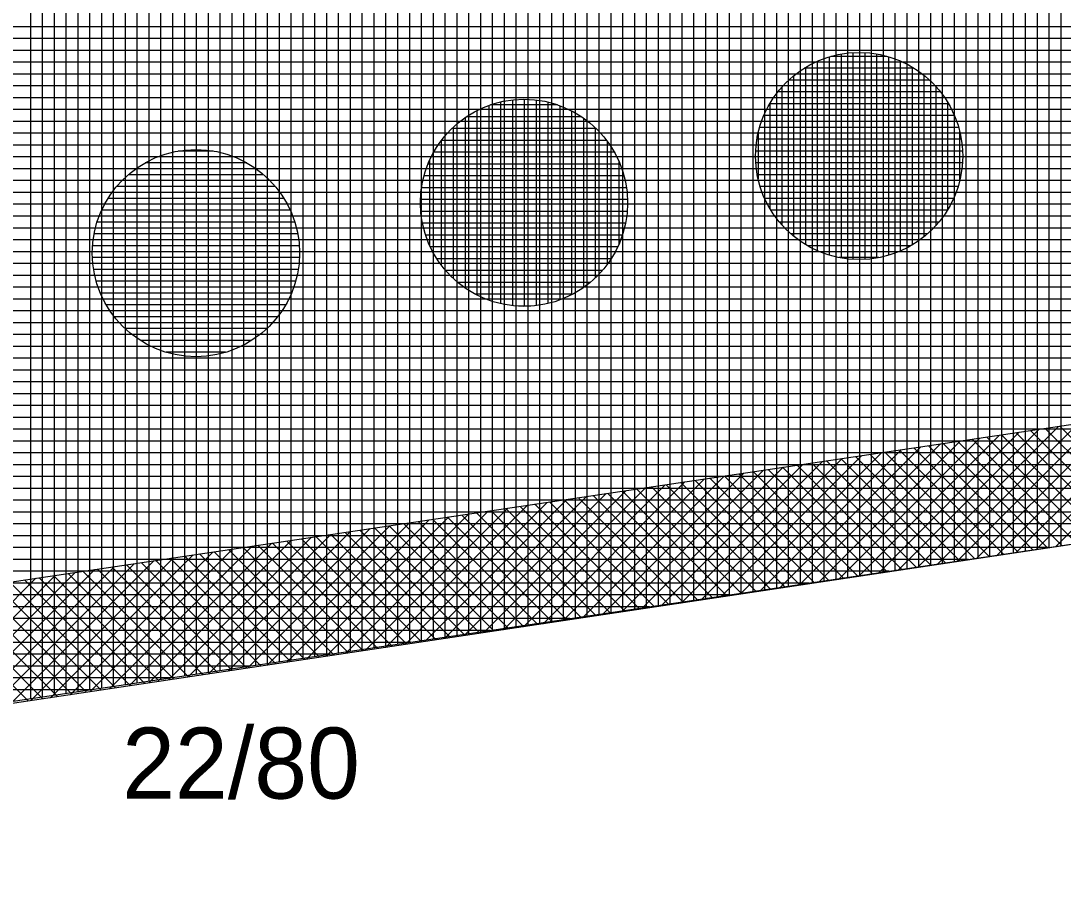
# Model space of a CAD drawing. Extents: x -565346 to -564154, y -1097386 to -1095620.
# Drawn here: x -564897.63 to -564880.03, y -1095809.07 to -1095794.48 of the extents above; entities that cross this region are included whole.
import ezdxf

# ---------------------------------------------------------------- set-up
doc = ezdxf.new("R2010")
doc.units = 0
for name, color, linetype in [('Vrstva 1', 7, 'Continuous'), ('Vrstva 40', 7, 'Continuous'), ('Vrstva 41', 7, 'Continuous'), ('Vrstva 42', 7, 'Continuous'), ('Vrstva 43', 7, 'Continuous'), ('Vrstva 44', 7, 'Continuous')]:
    doc.layers.add(name, color=color, linetype=linetype)

msp = doc.modelspace()

# ---------------------------------------------------------------- linework, layer by layer
at = {"layer": 'Vrstva 1'}
msp.add_line((-565025.24, -1095824.91), (-564877.52, -1095802.97), dxfattribs=at)
at = {"layer": 'Vrstva 41'}
for p, q in [((-564880.492, -1095803.416), (-564878.112, -1095801.036)), ((-564880.159, -1095803.366), (-564877.778, -1095800.985)), ((-564881.49, -1095803.566), (-564879.108, -1095801.184)), ((-564881.157, -1095803.516), (-564878.776, -1095801.135)), ((-564880.825, -1095803.466), (-564878.444, -1095801.086)), ((-564882.821, -1095803.766), (-564880.437, -1095801.382)), ((-564882.489, -1095803.716), (-564880.105, -1095801.332)), ((-564882.156, -1095803.666), (-564879.773, -1095801.283)), ((-564881.823, -1095803.616), (-564879.44, -1095801.234)), ((-564878.815, -1095803.165), (-564880.578, -1095801.402)), ((-564878.57, -1095803.128), (-564880.331, -1095801.366)), ((-564878.324, -1095803.091), (-564880.085, -1095801.329)), ((-564884.153, -1095803.966), (-564881.766, -1095801.579)), ((-564883.82, -1095803.916), (-564881.434, -1095801.53)), ((-564883.487, -1095803.866), (-564881.101, -1095801.48)), ((-564883.154, -1095803.816), (-564880.769, -1095801.431)), ((-564879.799, -1095803.312), (-564881.563, -1095801.549)), ((-564879.553, -1095803.275), (-564881.316, -1095801.512)), ((-564879.307, -1095803.238), (-564881.07, -1095801.476)), ((-564879.061, -1095803.201), (-564880.824, -1095801.439)), ((-564885.151, -1095804.116), (-564882.762, -1095801.727)), ((-564884.818, -1095804.066), (-564882.43, -1095801.678)), ((-564884.486, -1095804.016), (-564882.098, -1095801.628)), ((-564881.029, -1095803.497), (-564882.794, -1095801.732)), ((-564880.783, -1095803.46), (-564882.548, -1095801.695)), ((-564880.537, -1095803.423), (-564882.301, -1095801.658)), ((-564880.291, -1095803.386), (-564882.055, -1095801.622)), ((-564880.045, -1095803.349), (-564881.809, -1095801.585)), ((-564886.482, -1095804.316), (-564884.091, -1095801.924)), ((-564886.15, -1095804.266), (-564883.759, -1095801.875)), ((-564885.817, -1095804.216), (-564883.427, -1095801.826)), ((-564885.484, -1095804.166), (-564883.094, -1095801.776)), ((-564882.258, -1095803.681), (-564884.025, -1095801.915)), ((-564882.012, -1095803.645), (-564883.779, -1095801.878)), ((-564881.766, -1095803.608), (-564883.533, -1095801.841)), ((-564881.521, -1095803.571), (-564883.286, -1095801.805)), ((-564881.275, -1095803.534), (-564883.04, -1095801.768)), ((-564887.481, -1095804.466), (-564885.088, -1095802.072)), ((-564887.148, -1095804.416), (-564884.755, -1095802.023)), ((-564886.815, -1095804.366), (-564884.423, -1095801.974)), ((-564883.488, -1095803.866), (-564885.257, -1095802.097)), ((-564883.242, -1095803.829), (-564885.01, -1095802.061)), ((-564882.996, -1095803.792), (-564884.764, -1095802.024)), ((-564882.75, -1095803.755), (-564884.518, -1095801.988)), ((-564882.504, -1095803.718), (-564884.272, -1095801.951)), ((-564888.812, -1095804.666), (-564886.416, -1095802.27)), ((-564888.479, -1095804.616), (-564886.084, -1095802.22)), ((-564888.147, -1095804.566), (-564885.752, -1095802.171)), ((-564887.814, -1095804.516), (-564885.42, -1095802.122)), ((-564884.717, -1095804.051), (-564886.488, -1095802.28)), ((-564884.472, -1095804.014), (-564886.242, -1095802.244)), ((-564884.226, -1095803.977), (-564885.995, -1095802.207)), ((-564883.98, -1095803.94), (-564885.749, -1095802.171)), ((-564883.734, -1095803.903), (-564885.503, -1095802.134)), ((-564889.811, -1095804.816), (-564887.413, -1095802.418)), ((-564889.478, -1095804.766), (-564887.081, -1095802.368)), ((-564889.145, -1095804.716), (-564886.748, -1095802.319)), ((-564885.701, -1095804.198), (-564887.473, -1095802.427)), ((-564885.455, -1095804.162), (-564887.227, -1095802.39)), ((-564885.209, -1095804.125), (-564886.98, -1095802.353)), ((-564884.963, -1095804.088), (-564886.734, -1095802.317)), ((-564891.142, -1095805.015), (-564888.741, -1095802.615)), ((-564890.809, -1095804.965), (-564888.409, -1095802.566)), ((-564890.476, -1095804.916), (-564888.077, -1095802.516)), ((-564890.143, -1095804.866), (-564887.745, -1095802.467)), ((-564886.931, -1095804.383), (-564888.704, -1095802.609)), ((-564886.685, -1095804.346), (-564888.458, -1095802.573)), ((-564886.439, -1095804.309), (-564888.212, -1095802.536)), ((-564886.193, -1095804.272), (-564887.966, -1095802.5)), ((-564885.947, -1095804.235), (-564887.719, -1095802.463)), ((-564892.473, -1095805.215), (-564890.07, -1095802.812)), ((-564892.14, -1095805.165), (-564889.738, -1095802.763)), ((-564891.808, -1095805.115), (-564889.406, -1095802.714)), ((-564891.475, -1095805.065), (-564889.074, -1095802.664)), ((-564888.16, -1095804.568), (-564889.936, -1095802.792)), ((-564887.914, -1095804.531), (-564889.689, -1095802.756)), ((-564887.668, -1095804.494), (-564889.443, -1095802.719)), ((-564887.423, -1095804.457), (-564889.197, -1095802.683)), ((-564887.177, -1095804.42), (-564888.951, -1095802.646)), ((-564893.472, -1095805.365), (-564891.067, -1095802.96)), ((-564893.139, -1095805.315), (-564890.735, -1095802.911)), ((-564892.806, -1095805.265), (-564890.402, -1095802.862)), ((-564889.39, -1095804.752), (-564891.167, -1095802.975)), ((-564889.144, -1095804.715), (-564890.921, -1095802.939)), ((-564888.898, -1095804.679), (-564890.674, -1095802.902)), ((-564888.652, -1095804.642), (-564890.428, -1095802.866)), ((-564888.406, -1095804.605), (-564890.182, -1095802.829)), ((-564894.803, -1095805.565), (-564892.395, -1095803.158)), ((-564894.47, -1095805.515), (-564892.063, -1095803.108)), ((-564894.137, -1095805.465), (-564891.731, -1095803.059)), ((-564893.804, -1095805.415), (-564891.399, -1095803.01)), ((-564890.619, -1095804.937), (-564892.398, -1095803.158)), ((-564890.374, -1095804.9), (-564892.152, -1095803.122)), ((-564890.128, -1095804.863), (-564891.906, -1095803.085)), ((-564889.882, -1095804.826), (-564891.66, -1095803.048)), ((-564889.636, -1095804.789), (-564891.413, -1095803.012)), ((-564895.801, -1095805.715), (-564893.392, -1095803.306)), ((-564895.469, -1095805.665), (-564893.06, -1095803.256)), ((-564895.136, -1095805.615), (-564892.728, -1095803.207)), ((-564891.849, -1095805.122), (-564893.63, -1095803.341)), ((-564891.603, -1095805.085), (-564893.383, -1095803.304)), ((-564891.357, -1095805.048), (-564893.137, -1095803.268)), ((-564891.111, -1095805.011), (-564892.891, -1095803.231)), ((-564890.865, -1095804.974), (-564892.645, -1095803.195)), ((-564897.133, -1095805.915), (-564894.721, -1095803.503)), ((-564896.8, -1095805.865), (-564894.389, -1095803.454)), ((-564896.467, -1095805.815), (-564894.056, -1095803.404)), ((-564896.134, -1095805.765), (-564893.724, -1095803.355)), ((-564892.833, -1095805.269), (-564894.615, -1095803.487)), ((-564892.587, -1095805.232), (-564894.368, -1095803.451)), ((-564892.341, -1095805.195), (-564894.122, -1095803.414)), ((-564892.095, -1095805.159), (-564893.876, -1095803.378)), ((-564898.131, -1095806.065), (-564895.717, -1095803.651)), ((-564897.798, -1095806.015), (-564895.385, -1095803.602)), ((-564897.465, -1095805.965), (-564895.053, -1095803.552)), ((-564894.062, -1095805.454), (-564895.846, -1095803.67)), ((-564893.816, -1095805.417), (-564895.6, -1095803.634)), ((-564893.57, -1095805.38), (-564895.354, -1095803.597)), ((-564893.325, -1095805.343), (-564895.107, -1095803.56)), ((-564893.079, -1095805.306), (-564894.861, -1095803.524)), ((-564899.462, -1095806.265), (-564897.046, -1095803.848)), ((-564899.13, -1095806.215), (-564896.714, -1095803.799)), ((-564898.797, -1095806.165), (-564896.382, -1095803.75)), ((-564898.464, -1095806.115), (-564896.049, -1095803.7)), ((-564895.292, -1095805.639), (-564897.077, -1095803.853)), ((-564895.046, -1095805.602), (-564896.831, -1095803.817)), ((-564894.8, -1095805.565), (-564896.585, -1095803.78)), ((-564894.554, -1095805.528), (-564896.339, -1095803.743)), ((-564894.308, -1095805.491), (-564896.092, -1095803.707)), ((-564899.795, -1095806.315), (-564897.378, -1095803.898)), ((-564896.521, -1095805.823), (-564898.309, -1095804.036)), ((-564896.276, -1095805.786), (-564898.062, -1095803.999)), ((-564896.03, -1095805.749), (-564897.816, -1095803.963)), ((-564895.784, -1095805.712), (-564897.57, -1095803.926)), ((-564895.538, -1095805.676), (-564897.324, -1095803.89)), ((-564897.505, -1095805.971), (-564899.294, -1095804.182)), ((-564897.259, -1095805.934), (-564899.048, -1095804.146)), ((-564897.013, -1095805.897), (-564898.801, -1095804.109)), ((-564896.767, -1095805.86), (-564898.555, -1095804.073))]:
    msp.add_line(p, q, dxfattribs=at)
at = {"layer": 'Vrstva 42'}
msp.add_lwpolyline([(-564912.15, -1095808.17), (-564912.447, -1095806.136), (-564877.814, -1095800.992), (-564725.004, -1095771.664), (-564724.6, -1095773.56), (-564877.52, -1095802.97)], close=True, dxfattribs=at)
at = {"layer": 'Vrstva 43'}
for p, q in [((-564880.07, -1095788.189), (-564880.07, -1095803.349)), ((-564881.27, -1095788.367), (-564881.27, -1095803.527)), ((-564881.07, -1095788.337), (-564881.07, -1095803.497)), ((-564880.87, -1095788.307), (-564880.87, -1095803.468)), ((-564880.67, -1095788.278), (-564880.67, -1095803.438)), ((-564880.47, -1095788.248), (-564880.47, -1095803.408)), ((-564880.27, -1095788.218), (-564880.27, -1095803.378)), ((-564882.47, -1095788.545), (-564882.47, -1095803.705)), ((-564882.27, -1095788.515), (-564882.27, -1095803.675)), ((-564882.07, -1095788.486), (-564882.07, -1095803.646)), ((-564881.87, -1095788.456), (-564881.87, -1095803.616)), ((-564881.67, -1095788.426), (-564881.67, -1095803.586)), ((-564881.47, -1095788.397), (-564881.47, -1095803.557)), ((-564883.67, -1095788.723), (-564883.67, -1095803.883)), ((-564883.47, -1095788.694), (-564883.47, -1095803.854)), ((-564883.27, -1095788.664), (-564883.27, -1095803.824)), ((-564883.07, -1095788.634), (-564883.07, -1095803.794)), ((-564882.87, -1095788.604), (-564882.87, -1095803.765)), ((-564882.67, -1095788.575), (-564882.67, -1095803.735)), ((-564884.87, -1095788.901), (-564884.87, -1095804.062)), ((-564884.67, -1095788.872), (-564884.67, -1095804.032)), ((-564884.47, -1095788.842), (-564884.47, -1095804.002)), ((-564884.27, -1095788.812), (-564884.27, -1095803.973)), ((-564884.07, -1095788.783), (-564884.07, -1095803.943)), ((-564883.87, -1095788.753), (-564883.87, -1095803.913)), ((-564886.07, -1095789.08), (-564886.07, -1095804.24)), ((-564885.87, -1095789.05), (-564885.87, -1095804.21)), ((-564885.67, -1095789.02), (-564885.67, -1095804.18)), ((-564885.47, -1095788.991), (-564885.47, -1095804.151)), ((-564885.27, -1095788.961), (-564885.27, -1095804.121)), ((-564885.07, -1095788.931), (-564885.07, -1095804.091)), ((-564887.27, -1095789.258), (-564887.27, -1095804.418)), ((-564887.07, -1095789.228), (-564887.07, -1095804.388)), ((-564886.87, -1095789.198), (-564886.87, -1095804.359)), ((-564886.67, -1095789.169), (-564886.67, -1095804.329)), ((-564886.47, -1095789.139), (-564886.47, -1095804.299)), ((-564886.27, -1095789.109), (-564886.27, -1095804.27)), ((-564888.27, -1095789.406), (-564888.27, -1095804.567)), ((-564888.07, -1095789.377), (-564888.07, -1095804.537)), ((-564887.87, -1095789.347), (-564887.87, -1095804.507)), ((-564887.67, -1095789.317), (-564887.67, -1095804.478)), ((-564887.47, -1095789.288), (-564887.47, -1095804.448)), ((-564889.47, -1095789.585), (-564889.47, -1095804.745)), ((-564889.27, -1095789.555), (-564889.27, -1095804.715)), ((-564889.07, -1095789.525), (-564889.07, -1095804.685)), ((-564888.87, -1095789.495), (-564888.87, -1095804.656)), ((-564888.67, -1095789.466), (-564888.67, -1095804.626)), ((-564888.47, -1095789.436), (-564888.47, -1095804.596)), ((-564890.67, -1095789.763), (-564890.67, -1095804.923)), ((-564890.47, -1095789.733), (-564890.47, -1095804.893)), ((-564890.27, -1095789.703), (-564890.27, -1095804.864)), ((-564890.07, -1095789.674), (-564890.07, -1095804.834)), ((-564889.87, -1095789.644), (-564889.87, -1095804.804)), ((-564889.67, -1095789.614), (-564889.67, -1095804.775)), ((-564891.87, -1095789.941), (-564891.87, -1095805.101)), ((-564891.67, -1095789.911), (-564891.67, -1095805.072)), ((-564891.47, -1095789.882), (-564891.47, -1095805.042)), ((-564891.27, -1095789.852), (-564891.27, -1095805.012)), ((-564891.07, -1095789.822), (-564891.07, -1095804.983)), ((-564890.87, -1095789.792), (-564890.87, -1095804.953)), ((-564893.07, -1095790.119), (-564893.07, -1095805.28)), ((-564892.87, -1095790.089), (-564892.87, -1095805.25)), ((-564892.67, -1095790.06), (-564892.67, -1095805.22)), ((-564892.47, -1095790.03), (-564892.47, -1095805.19)), ((-564892.27, -1095790), (-564892.27, -1095805.161)), ((-564892.07, -1095789.971), (-564892.07, -1095805.131)), ((-564894.27, -1095790.297), (-564894.27, -1095805.458)), ((-564894.07, -1095790.268), (-564894.07, -1095805.428)), ((-564893.87, -1095790.238), (-564893.87, -1095805.398)), ((-564893.67, -1095790.208), (-564893.67, -1095805.369)), ((-564893.47, -1095790.179), (-564893.47, -1095805.339)), ((-564893.27, -1095790.149), (-564893.27, -1095805.309)), ((-564895.47, -1095790.476), (-564895.47, -1095805.636)), ((-564895.27, -1095790.446), (-564895.27, -1095805.606)), ((-564895.07, -1095790.416), (-564895.07, -1095805.577)), ((-564894.87, -1095790.386), (-564894.87, -1095805.547)), ((-564894.67, -1095790.357), (-564894.67, -1095805.517)), ((-564894.47, -1095790.327), (-564894.47, -1095805.487)), ((-564896.67, -1095790.654), (-564896.67, -1095805.814)), ((-564896.47, -1095790.624), (-564896.47, -1095805.785)), ((-564896.27, -1095790.594), (-564896.27, -1095805.755)), ((-564896.07, -1095790.565), (-564896.07, -1095805.725)), ((-564895.87, -1095790.535), (-564895.87, -1095805.695)), ((-564895.67, -1095790.505), (-564895.67, -1095805.666)), ((-564897.47, -1095790.773), (-564897.47, -1095805.933)), ((-564897.27, -1095790.743), (-564897.27, -1095805.903)), ((-564897.07, -1095790.713), (-564897.07, -1095805.874)), ((-564896.87, -1095790.683), (-564896.87, -1095805.844)), ((-564833.802, -1095794.58), (-564923.109, -1095794.58)), ((-564834.845, -1095794.78), (-564924.456, -1095794.78)), ((-564835.887, -1095794.98), (-564925.802, -1095794.98)), ((-564836.929, -1095795.18), (-564927.149, -1095795.18)), ((-564837.971, -1095795.38), (-564928.496, -1095795.38)), ((-564839.013, -1095795.58), (-564929.843, -1095795.58)), ((-564840.055, -1095795.78), (-564931.189, -1095795.78)), ((-564841.097, -1095795.98), (-564932.536, -1095795.98)), ((-564842.14, -1095796.18), (-564933.883, -1095796.18)), ((-564843.182, -1095796.38), (-564935.23, -1095796.38)), ((-564844.224, -1095796.58), (-564936.577, -1095796.58)), ((-564845.266, -1095796.78), (-564937.923, -1095796.78)), ((-564846.308, -1095796.98), (-564939.27, -1095796.98)), ((-564847.35, -1095797.18), (-564940.617, -1095797.18)), ((-564848.392, -1095797.38), (-564941.964, -1095797.38)), ((-564849.434, -1095797.58), (-564943.31, -1095797.58)), ((-564850.477, -1095797.78), (-564944.657, -1095797.78)), ((-564851.519, -1095797.98), (-564946.004, -1095797.98)), ((-564852.561, -1095798.18), (-564947.351, -1095798.18)), ((-564853.603, -1095798.38), (-564948.697, -1095798.38)), ((-564854.645, -1095798.58), (-564950.044, -1095798.58)), ((-564855.687, -1095798.78), (-564951.391, -1095798.78)), ((-564856.729, -1095798.98), (-564952.738, -1095798.98)), ((-564857.772, -1095799.18), (-564954.085, -1095799.18)), ((-564858.814, -1095799.38), (-564955.431, -1095799.38)), ((-564859.856, -1095799.58), (-564956.778, -1095799.58)), ((-564860.898, -1095799.78), (-564958.125, -1095799.78)), ((-564861.94, -1095799.98), (-564959.472, -1095799.98)), ((-564862.982, -1095800.18), (-564960.818, -1095800.18)), ((-564864.024, -1095800.38), (-564962.165, -1095800.38)), ((-564865.066, -1095800.58), (-564963.512, -1095800.58)), ((-564866.109, -1095800.78), (-564964.859, -1095800.78)), ((-564867.151, -1095800.98), (-564966.206, -1095800.98)), ((-564868.193, -1095801.18), (-564967.552, -1095801.18)), ((-564869.235, -1095801.38), (-564968.899, -1095801.38)), ((-564870.277, -1095801.58), (-564970.246, -1095801.58)), ((-564871.319, -1095801.78), (-564971.593, -1095801.78)), ((-564872.361, -1095801.98), (-564972.939, -1095801.98)), ((-564873.404, -1095802.18), (-564974.286, -1095802.18)), ((-564874.446, -1095802.38), (-564975.633, -1095802.38)), ((-564875.488, -1095802.58), (-564976.98, -1095802.58)), ((-564876.53, -1095802.78), (-564978.326, -1095802.78)), ((-564877.587, -1095802.98), (-564979.673, -1095802.98)), ((-564878.934, -1095803.18), (-564981.02, -1095803.18)), ((-564880.28, -1095803.38), (-564982.367, -1095803.38)), ((-564881.627, -1095803.58), (-564983.714, -1095803.58)), ((-564882.974, -1095803.78), (-564985.06, -1095803.78)), ((-564884.32, -1095803.98), (-564986.407, -1095803.98)), ((-564885.667, -1095804.18), (-564987.754, -1095804.18)), ((-564887.013, -1095804.38), (-564989.101, -1095804.38)), ((-564888.36, -1095804.58), (-564990.447, -1095804.58)), ((-564889.707, -1095804.78), (-564991.794, -1095804.78)), ((-564891.053, -1095804.98), (-564993.141, -1095804.98)), ((-564892.4, -1095805.18), (-564994.488, -1095805.18)), ((-564893.746, -1095805.38), (-564995.835, -1095805.38)), ((-564895.093, -1095805.58), (-564997.181, -1095805.58)), ((-564896.439, -1095805.78), (-564998.528, -1095805.78))]:
    msp.add_line(p, q, dxfattribs=at)
msp.add_lwpolyline([(-564584.17, -1095730.99), (-564361.01, -1095672.63), (-564329.81, -1095662.26), (-564326.21, -1095642.73), (-564394.52, -1095662.95), (-564454.33, -1095677.56), (-564516.6, -1095690.89), (-564574.04, -1095705.03), (-564590.74, -1095715.12), (-564631.48, -1095731.18), (-564693.31, -1095752.31), (-564772.2, -1095768.91), (-564879.81, -1095788.15), (-565039.47, -1095811.86), (-565040.85, -1095849.94), (-565025.81, -1095848.33), (-565025.24, -1095824.91), (-564877.52, -1095802.97), (-564694, -1095767.75), (-564603.8, -1095739.23), (-564594.74, -1095734.52)], close=True, dxfattribs=at)
at = {"layer": 'Vrstva 44'}
for p, q in [((-564883.78, -1095795.041), (-564883.78, -1095798.485)), ((-564883.58, -1095795.019), (-564883.58, -1095798.509)), ((-564883.38, -1095795.018), (-564883.38, -1095798.51)), ((-564883.18, -1095795.041), (-564883.18, -1095798.489)), ((-564884.18, -1095795.165), (-564884.18, -1095798.363)), ((-564883.98, -1095795.09), (-564883.98, -1095798.439)), ((-564883.004, -1095795.08), (-564883.95, -1095795.08)), ((-564882.98, -1095795.086), (-564882.98, -1095798.441)), ((-564882.78, -1095795.159), (-564882.78, -1095798.368)), ((-564884.58, -1095795.41), (-564884.58, -1095798.119)), ((-564882.55, -1095795.28), (-564884.401, -1095795.28)), ((-564884.38, -1095795.268), (-564884.38, -1095798.259)), ((-564882.58, -1095795.262), (-564882.58, -1095798.268)), ((-564882.38, -1095795.399), (-564882.38, -1095798.127)), ((-564882.288, -1095795.48), (-564884.663, -1095795.48)), ((-564882.18, -1095795.589), (-564882.18, -1095797.942)), ((-564882.102, -1095795.68), (-564884.846, -1095795.68)), ((-564884.78, -1095795.599), (-564884.78, -1095797.927)), ((-564889.73, -1095795.91), (-564889.73, -1095799.197)), ((-564888.568, -1095795.9), (-564889.7, -1095795.9)), ((-564889.53, -1095795.851), (-564889.53, -1095799.258)), ((-564889.33, -1095795.817), (-564889.33, -1095799.292)), ((-564889.13, -1095795.805), (-564889.13, -1095799.302)), ((-564888.93, -1095795.817), (-564888.93, -1095799.29)), ((-564888.73, -1095795.853), (-564888.73, -1095799.255)), ((-564888.53, -1095795.914), (-564888.53, -1095799.196)), ((-564881.966, -1095795.88), (-564884.984, -1095795.88)), ((-564884.98, -1095795.873), (-564884.98, -1095797.654)), ((-564881.98, -1095795.857), (-564881.98, -1095797.675)), ((-564890.13, -1095796.117), (-564890.13, -1095798.991)), ((-564888.161, -1095796.1), (-564890.105, -1095796.1)), ((-564889.93, -1095795.996), (-564889.93, -1095799.112)), ((-564888.33, -1095796.001), (-564888.33, -1095799.106)), ((-564888.13, -1095796.123), (-564888.13, -1095798.985)), ((-564881.864, -1095796.08), (-564885.083, -1095796.08)), ((-564887.914, -1095796.3), (-564890.353, -1095796.3)), ((-564890.33, -1095796.276), (-564890.33, -1095798.83)), ((-564887.93, -1095796.286), (-564887.93, -1095798.822)), ((-564881.794, -1095796.28), (-564885.154, -1095796.28)), ((-564885.18, -1095796.38), (-564885.18, -1095797.152)), ((-564881.78, -1095796.333), (-564881.78, -1095797.2)), ((-564887.74, -1095796.5), (-564890.53, -1095796.5)), ((-564890.53, -1095796.5), (-564890.53, -1095798.607)), ((-564887.73, -1095796.513), (-564887.73, -1095798.598)), ((-564881.749, -1095796.48), (-564885.2, -1095796.48)), ((-564895.27, -1095796.76), (-564895.27, -1095800.047)), ((-564895.07, -1095796.701), (-564895.07, -1095800.108)), ((-564894.385, -1095796.68), (-564894.972, -1095796.68)), ((-564894.87, -1095796.667), (-564894.87, -1095800.142)), ((-564894.67, -1095796.655), (-564894.67, -1095800.152)), ((-564894.47, -1095796.667), (-564894.47, -1095800.14)), ((-564894.27, -1095796.703), (-564894.27, -1095800.105)), ((-564894.07, -1095796.764), (-564894.07, -1095800.046)), ((-564887.607, -1095796.7), (-564890.66, -1095796.7)), ((-564881.728, -1095796.68), (-564885.222, -1095796.68)), ((-564895.67, -1095796.967), (-564895.67, -1095799.841)), ((-564893.817, -1095796.88), (-564895.53, -1095796.88)), ((-564895.47, -1095796.846), (-564895.47, -1095799.962)), ((-564893.87, -1095796.851), (-564893.87, -1095799.956)), ((-564893.67, -1095796.973), (-564893.67, -1095799.835)), ((-564887.513, -1095796.9), (-564890.755, -1095796.9)), ((-564890.73, -1095796.838), (-564890.73, -1095798.272)), ((-564887.53, -1095796.855), (-564887.53, -1095798.248)), ((-564881.728, -1095796.88), (-564885.219, -1095796.88)), ((-564895.87, -1095797.126), (-564895.87, -1095799.68)), ((-564893.532, -1095797.08), (-564895.816, -1095797.08)), ((-564893.47, -1095797.136), (-564893.47, -1095799.672)), ((-564887.446, -1095797.1), (-564890.823, -1095797.1)), ((-564881.754, -1095797.08), (-564885.193, -1095797.08)), ((-564896.07, -1095797.35), (-564896.07, -1095799.457)), ((-564893.333, -1095797.28), (-564896.013, -1095797.28)), ((-564887.404, -1095797.3), (-564890.865, -1095797.3)), ((-564881.804, -1095797.28), (-564885.145, -1095797.28)), ((-564893.19, -1095797.48), (-564896.159, -1095797.48)), ((-564893.27, -1095797.363), (-564893.27, -1095799.448)), ((-564887.385, -1095797.5), (-564890.882, -1095797.5)), ((-564881.879, -1095797.48), (-564885.071, -1095797.48)), ((-564896.27, -1095797.688), (-564896.27, -1095799.122)), ((-564893.082, -1095797.68), (-564896.267, -1095797.68)), ((-564893.07, -1095797.705), (-564893.07, -1095799.098)), ((-564887.391, -1095797.7), (-564890.876, -1095797.7)), ((-564881.983, -1095797.68), (-564884.963, -1095797.68)), ((-564893.005, -1095797.88), (-564896.342, -1095797.88)), ((-564882.129, -1095797.88), (-564884.821, -1095797.88)), ((-564887.421, -1095797.9), (-564890.848, -1095797.9)), ((-564892.956, -1095798.08), (-564896.392, -1095798.08)), ((-564887.474, -1095798.1), (-564890.796, -1095798.1)), ((-564882.322, -1095798.08), (-564884.625, -1095798.08)), ((-564892.931, -1095798.28), (-564896.419, -1095798.28)), ((-564887.552, -1095798.3), (-564890.716, -1095798.3)), ((-564882.603, -1095798.28), (-564884.344, -1095798.28)), ((-564892.927, -1095798.48), (-564896.422, -1095798.48)), ((-564887.664, -1095798.5), (-564890.604, -1095798.5)), ((-564883.14, -1095798.48), (-564883.809, -1095798.48)), ((-564892.947, -1095798.68), (-564896.401, -1095798.68)), ((-564887.814, -1095798.7), (-564890.456, -1095798.7)), ((-564892.991, -1095798.88), (-564896.356, -1095798.88)), ((-564888.019, -1095798.9), (-564890.25, -1095798.9)), ((-564893.062, -1095799.08), (-564896.287, -1095799.08)), ((-564888.318, -1095799.1), (-564889.953, -1095799.1)), ((-564893.161, -1095799.28), (-564896.189, -1095799.28)), ((-564889.016, -1095799.3), (-564889.227, -1095799.3)), ((-564893.296, -1095799.48), (-564896.052, -1095799.48)), ((-564893.478, -1095799.68), (-564895.871, -1095799.68)), ((-564893.736, -1095799.88), (-564895.613, -1095799.88)), ((-564894.177, -1095800.08), (-564895.177, -1095800.08))]:
    msp.add_line(p, q, dxfattribs=at)
for centre in [(-564883.474, -1095796.764), (-564889.134, -1095797.554), (-564894.674, -1095798.404)]:
    msp.add_circle(centre, 1.75, dxfattribs=at)

# ---------------------------------------------------------------- texts
at = {"layer": 'Vrstva 40'}
msp.add_text('22/80', height=1.2, dxfattribs=at).set_placement((-564895.92, -1095807.62))

doc.saveas('drawing.dxf')
